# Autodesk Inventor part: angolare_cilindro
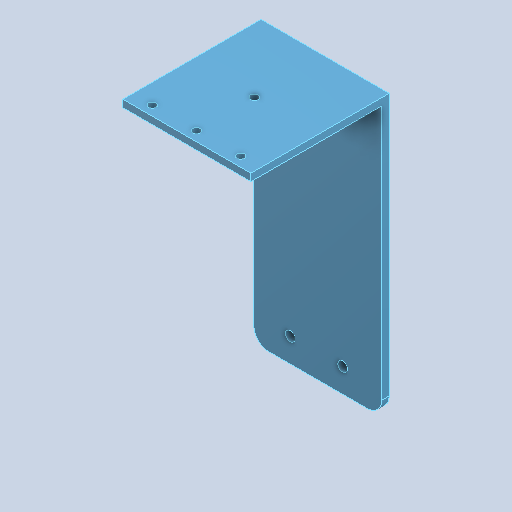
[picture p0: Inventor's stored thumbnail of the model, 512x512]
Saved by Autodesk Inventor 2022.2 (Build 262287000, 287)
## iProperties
Created: 2024-10
Part Number: angolare_cilindro
Material: Acciaio inossidabile
Document SubType Name: Modeling
Designer: 18907419
Density: 8 g/cm^3
Appearance: Default
Author: 18907419
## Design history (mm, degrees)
feature "Solido1"
node "Solido2"
